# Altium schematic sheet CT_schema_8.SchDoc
size 258 x 245 mm
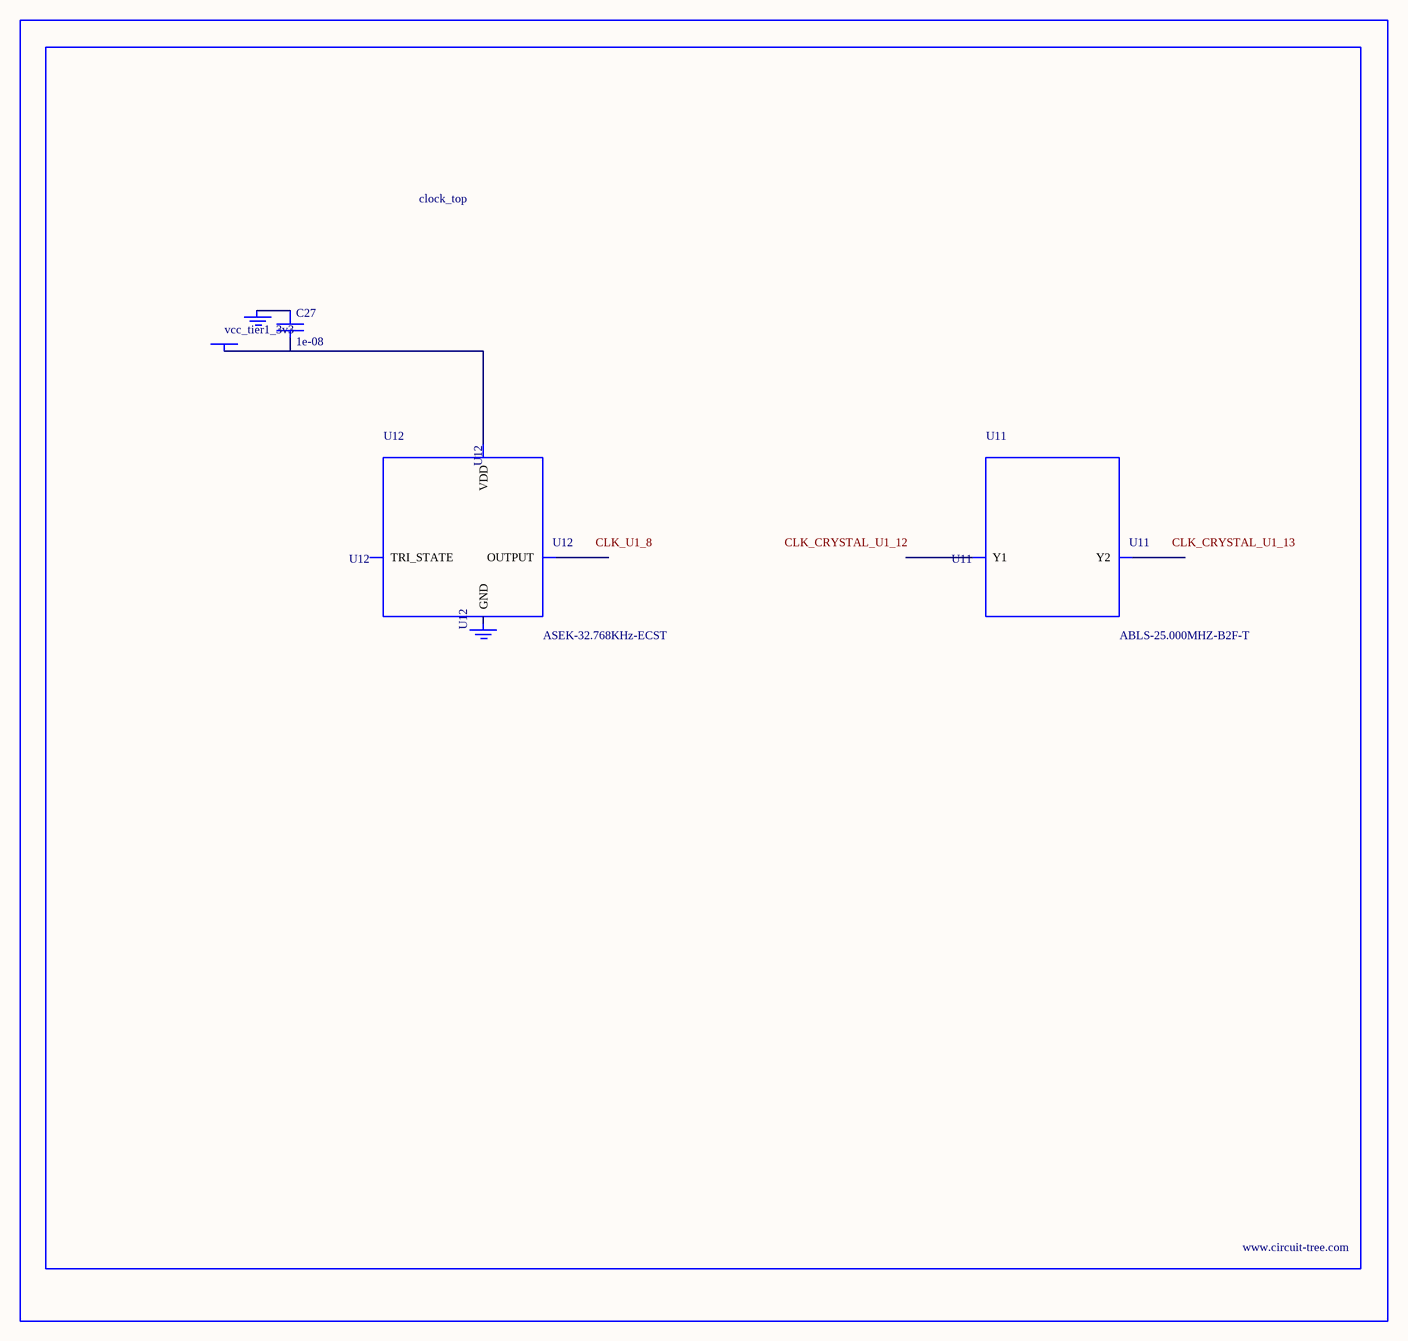
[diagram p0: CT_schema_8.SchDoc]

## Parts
BORDER7  (no value)
C27  1e-08  [C0402]
GND_INSTANCE_7_0  (no value)
GND_INSTANCE_7_1  (no value)
POWER_INSTANCE_7_0  vcc_tier1_3v3
U11  ABLS-25.000MHZ-B2F-T  [ABLS-25.000MHZ-B2F-T]
U12  ASEK-32.768KHz-ECST  [ASEK]

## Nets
NetC27_1: C27.1 GND_INSTANCE_7_0.0(GND)
NetC27_2: C27.2 POWER_INSTANCE_7_0.0(PWR) U12.4(VDD)

Not connected (* = marked no-connect by the designer): GND_INSTANCE_7_1 0(GND); U11 1(Y1) 2(Y2); U12 1(TRI_STATE) 2(GND) 3(OUTPUT)

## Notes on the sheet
- Labels drawn without touching a wire or pin: CLK_CRYSTAL_U1_12, CLK_CRYSTAL_U1_13, CLK_U1_8

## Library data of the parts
BORDER7 = BORDER_PAGE7
C27 = C0402C103K3RAC
GND_INSTANCE_7_0 GND_INSTANCE_7_1 = GND
POWER_INSTANCE_7_0 = PWR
